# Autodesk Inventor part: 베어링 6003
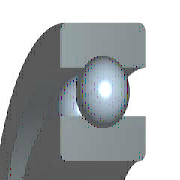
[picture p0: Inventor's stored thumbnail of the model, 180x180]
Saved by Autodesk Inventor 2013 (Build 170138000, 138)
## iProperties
IsCustomPart: 1
Company: 한국ATC센터
Created: 2014-07
Part Number: 베어링 6003
Material: Steel, Mild
Description: 깊은 그루브 볼 베어링
Document SubType Name: Modeling
Standard: KS B 2023
Designer: KYOUNG IL JANG
Standards Organization: KS
Language: ko-KR
Size Designation: 6003 - 17 x 35 x 10
Categories: <MemberInstance><Categories><Category DisplayName="샤프트 부품" InternalName="7f7aeb1f-a693-4053-b835-cee3144e0d98" Mnemonic="SHFT"><Category DisplayName="베어링" Inter
Density: 1 g/cm^3
Author: KYOUNG IL JANG
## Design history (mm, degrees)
revolve "본체" stored, may be unused: angle "d6" = 90 deg
revolve "볼" stored, may be unused: angle "d7" = 90 deg
pattern_circular "IDS_ARRAYBALL[SIMPL:T]" dims angle "d3" = 360 deg
body "Solid1"
sketch "스케치" dims "d0" = 4.68 (= -0.26 x WD + 0.26 x BD)
  geometry: L1 (2.66, 13)-(7.34, 13); L2 (5, 13)-(5, 10.66); L3 (5, 13)-(5, 15.34); L4 (3.261, 11.434)-(0, 11.434); L5 (0, 8.5)-(10, 8.5); L6 (3.261, 14.566)-(0, 14.566); L7 (0, 17.5)-(10, 17.5); L8 (10, 8.5)-(10, 11.434); L9 (6.739, 11.434)-(10, 11.434); L10 (6.739, 14.566)-(10, 14.566); L11 (10, 17.5)-(10, 14.566); L12 (-1.4, 0)-(8.4, 0) reference; L13 (0, -0.3)-(0, 5.3) reference
  constraints: 22 end point, 4 point on line, 2 collinear, 2 perpendicular, 2 symmetric about line, 1 midpoint, 1 parallel, 14 other
  dimensions: "d9" = 17 diameter of L5 L12 (= WD); "d11" = 35 diameter of L7 L12 (= BD); "d12" = 10 distance between parallel lines of L8 L13 (= KB); "d13" = 22.868 diameter of L9 L12 (= 0.326 x BD + 0.674 x WD)
fillet "모깎기1" dims "d1" = 0.3 (= KRS)
other parameters: "WD" = 17 [user parameter; used in 5 equation terms], "BD" = 35 [user parameter; used in 5 equation terms], "KB" = 10 [user parameter; used in 1 equation term], "KRS" = 0.3 [user parameter; used in 1 equation term], "d4" = 0, "d5" = 0, "d8" = 0, "d14" = 0, "d15" = 0, "BBA" = 0 [user parameter], "BC0" = 3250000 [user parameter], "BC" = 6050000 [user parameter], "BR" = 17.5 (= 0.5 x BD) [user parameter], "WR" = 8.5 (= 0.5 x WD) [user parameter]
